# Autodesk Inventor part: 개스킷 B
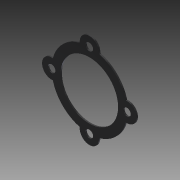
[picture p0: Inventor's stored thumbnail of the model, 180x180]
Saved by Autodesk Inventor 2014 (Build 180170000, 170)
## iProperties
Created: 2020-03
Part Number: 개스킷 B
Material: 고무
Document SubType Name: Modeling
Designer: mduedu
Density: 0.93 g/cm^3
Mass: 1.13966 g
Surface Area: 28.6179 cm^2
Volume: 1.22544 cm^3
Appearance: Rubber - Black - Version 1.1
Author: mduedu
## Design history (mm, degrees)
sketch "스케치1" dims "d1" = 55
  geometry: C1 r 21 at (0, 0); C2 r 7 at (0, 27.5); C3 r 7 at (-23.816, -13.75); C4 r 7 at (23.816, -13.75); 2 further points
  constraints: 4 centre point, 2 coincident, 2 vertical alignment, 9 other
  dimensions: "d0" = 42 diameter of C1; "d2" = 14 diameter of C2; "d5" = 360 deg dimension on point (0, 0) C2.centre (derived)
extrude "돌출1" new body sketch "스케치1" distance "d7" = 1; taper "d8" = 0 deg
extrude "돌출3" join sketch "스케치1" stored distance "d19" = 10; taper "d20" = 0 deg
fillet "모깎기1" dims "d11" = 1
extrude "돌출2" cut sketch "스케치1" stored distance "d9" = 1; taper "d10" = 0 deg
sketch "스케치2"
  geometry: C1 r 21 at (0, 0) reference; A1 r 7 centre (0, 27.5) between (6.999, 27.373) and (-6.999, 27.373) reference; A2 r 27.5 centre (0, 0) between (26.609, 6.943) and (7.718, 26.395) reference; A3 r 1 centre (7.999, 27.355) between (6.999, 27.373) and (7.718, 26.395) reference; A4 r 7 centre (0, 27.5) between (6.999, 27.373) and (-6.999, 27.373) reference; A5 r 1 centre (-7.999, 27.355) between (-7.718, 26.395) and (-6.999, 27.373) reference; A6 r 7 centre (0, -27.5) between (-6.943, -26.609) and (6.943, -26.609) reference; A7 r 7 centre (-27.5, 0) between (-26.609, 6.943) and (-26.609, -6.943) reference; A8 r 7 centre (27.5, 0) between (26.609, -6.943) and (26.609, 6.943) reference; A9 r 27.5 centre (0, 0) between (-26.609, -6.943) and (-6.943, -26.609) reference; A10 r 27.5 centre (0, 0) between (6.943, -26.609) and (26.609, -6.943) reference; A11 r 27.5 centre (0, 0) between (-7.718, 26.395) and (-26.609, 6.943) reference; 4 further points
hole "구멍1" sketch "스케치2" diameter "d12" = 5.5; stored, may be unused: countersink angle "d16" = 90 deg, drill point angle "d18" = 118 deg; dims "d13" = 6, "d14" = 4, "d15" = 2, "d17" = 8
node "솔리드1"
pattern_circular "원형 패턴1" dims angle "d22" = 360 deg
node "투영된 루프1"
